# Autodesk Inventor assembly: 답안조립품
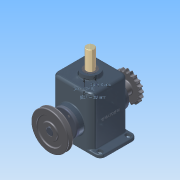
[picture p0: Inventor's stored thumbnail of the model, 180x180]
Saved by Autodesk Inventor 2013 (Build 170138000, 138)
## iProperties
Created: 2015-04
Part Number: 답안조립품
Document SubType Name: Assembly
Designer: Administrator
Mass: 8579 g
Surface Area: 4386.44 cm^2
Volume: 1982.5 cm^3
Density: 4.32736 g/cm^3
Author: Administrator
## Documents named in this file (15)
- C:\Documents and Settings\Administrator\바탕 화면\350305V1034\답안조립품.iam
- C:\Documents and Settings\Administrator\바탕 화면\350305V1034\본체.ipt
- C:\Documents and Settings\Administrator\바탕 화면\350305V1034\커버.ipt
- C:\Documents and Settings\Administrator\바탕 화면\350305V1034\베어링 6205.ipt
- C:\Documents and Settings\Administrator\바탕 화면\350305V1034\편심축.ipt
- C:\Documents and Settings\Administrator\바탕 화면\350305V1034\M4x0.5.ipt
- C:\Documents and Settings\Administrator\바탕 화면\350305V1034\오일실.ipt
- C:\Documents and Settings\Administrator\바탕 화면\350305V1034\부시.ipt
- C:\Documents and Settings\Administrator\바탕 화면\350305V1034\슬라이드.ipt
- C:\Documents and Settings\Administrator\바탕 화면\350305V1034\V-벨트풀리.ipt
- C:\Documents and Settings\Administrator\바탕 화면\350305V1034\키 8x8.ipt
- C:\Documents and Settings\Administrator\바탕 화면\350305V1034\체인 스프로킷.ipt
- C:\Documents and Settings\Administrator\바탕 화면\350305V1034\멈춤링.ipt
- C:\Documents and Settings\Administrator\바탕 화면\350305V1034\멈춤나사 M5x0.5.ipt
- C:\Documents and Settings\Administrator\바탕 화면\350305V1034\가변스프링.ipt
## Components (9 placed, 4 different names)
1. V-벨트풀리:1 — 플러쉬:3, 각도:3
2. 5-체인 스프로킷:1 — 플러쉬:4, 각도:4
3. 가변스프링:1
4. M4x0.5:1
5. M4x0.5:3
6. M4x0.5:4
7. M4x0.5:2
8. M4x0.5:5
9. M4x0.5:6
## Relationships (4: Flush 2, Angle 2)
- 플러쉬:3 [Flush]: V-벨트풀리:1
- 각도:3 [Angle]: V-벨트풀리:1
- 플러쉬:4 [Flush]: 5-체인 스프로킷:1
- 각도:4 [Angle]: 5-체인 스프로킷:1
